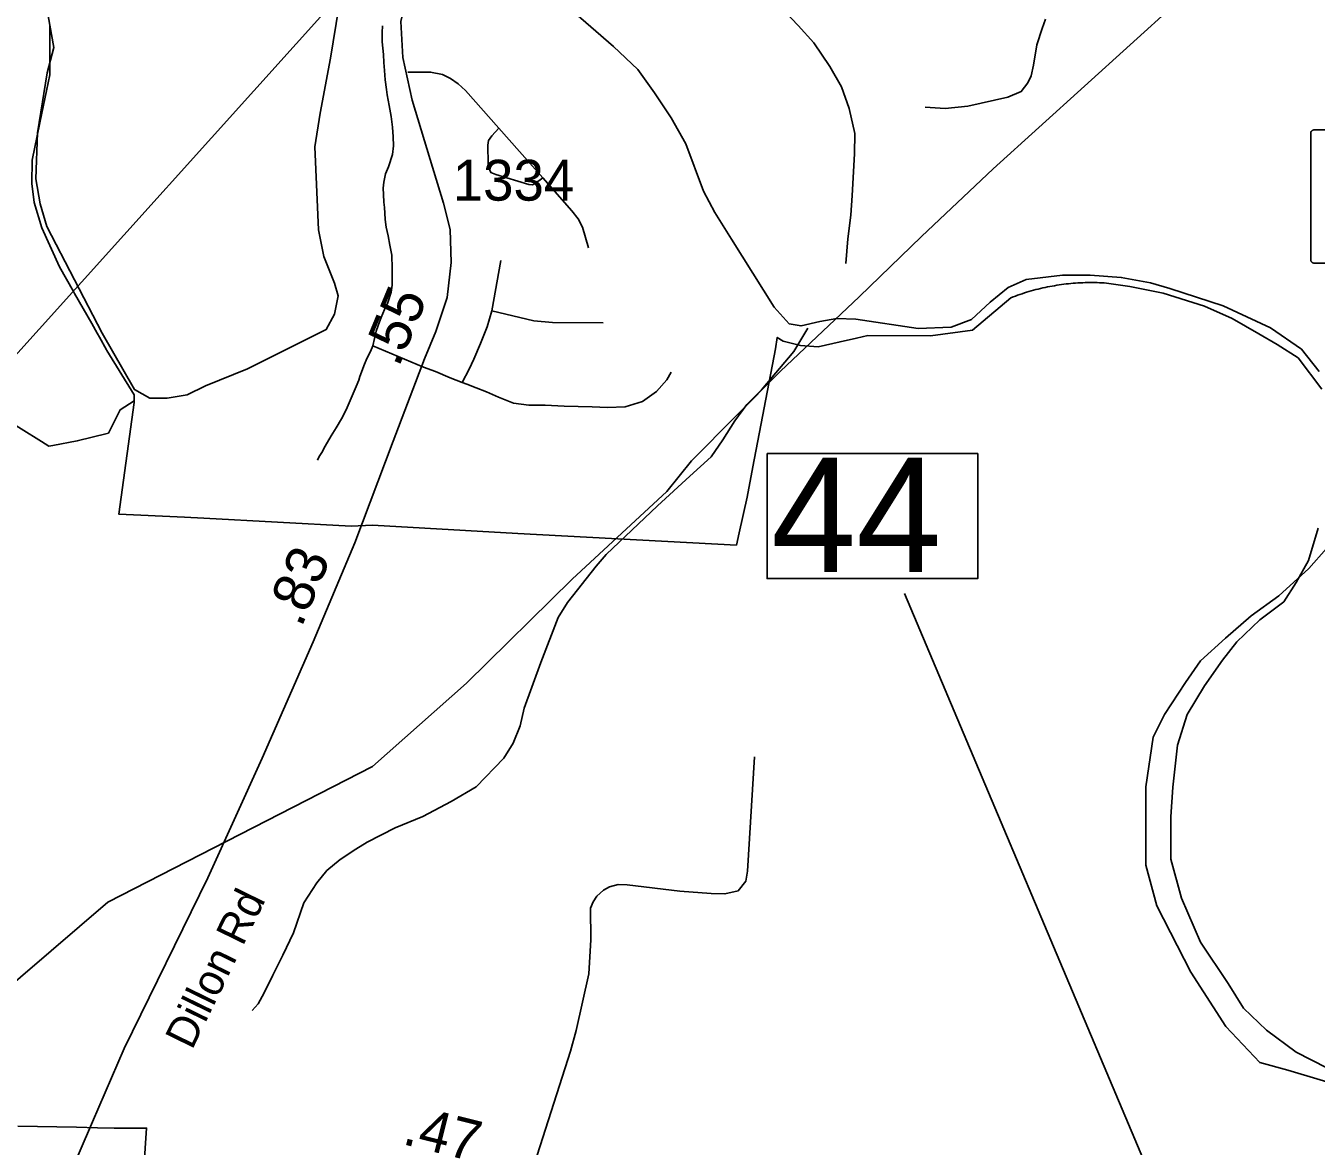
# Model space of a CAD drawing. Extents: x 1662474 to 1856135, y 779280 to 917889.
# Drawn here: x 1720709 to 1724654, y 812795 to 816221 of the extents above; entities that cross this region are included whole.
import ezdxf

# ---------------------------------------------------------------- set-up
doc = ezdxf.new("R2010")
doc.units = 0
for name, color, linetype in [('Exist Boundary Political City Limit New', 7, 'Continuous'), ('Exist Hydrographic Creek Single Shore', 7, 'Continuous'), ('Exist Hydrographic Misc Water Feature', 7, 'Continuous'), ('Exist Road Non-System Type 51', 7, 'Continuous'), ('Exist Road Primary NC Shield Bike CELL', 7, 'Continuous'), ('Exist Road Secondary Mileage Hundredths English Label', 7, 'Continuous'), ('Exist Road Secondary Mileage Tenths English Label', 7, 'Continuous'), ('Exist Road Secondary Structure Standard Bridge Number Label', 7, 'Continuous'), ('Exist Road Secondary Type 51 Attributed', 7, 'Continuous'), ('Exist Road Secondary Type 51 Label', 7, 'Continuous'), ('Exist Road Secondary Type 51 Number Label', 7, 'Continuous'), ('Exist Utilities Electrical Transmission Line', 7, 'Continuous'), ('Map Preparation Boundary City Limit Buffer Line', 7, 'Continuous')]:
    doc.layers.add(name, color=color, linetype=linetype)

msp = doc.modelspace()

# ---------------------------------------------------------------- linework, layer by layer
at = {"layer": 'Exist Boundary Political City Limit New'}
for points in [[(1720782.5, 816222.6), (1720782.4, 816071.8)], [(1720782.4, 816071.8), (1720782.5, 816222.6)], [(1720782.4, 816071.8), (1720782.4, 816071.2), (1720751.6, 815924.1), (1720728.6, 815810.6), (1720728.6, 815810), (1720727.2, 815739.2), (1720727.2, 815738.6), (1720734.4, 815681.2), (1720757.6, 815603.7), (1720811.9, 815484), (1720854.9, 815408.6), (1720858.2, 815402.8), (1720910.4, 815310.6), (1720927.1, 815281.2), (1720934, 815269.1), (1720955.6, 815230.8), (1720957, 815228.3), (1721040.6, 815093.2), (1721040.6, 815092.6), (1721040, 815074.6)], [(1721040, 815074.6), (1721040.6, 815092.6), (1721040.6, 815093.2), (1720957, 815228.3), (1720955.6, 815230.8), (1720934, 815269.1), (1720927.1, 815281.2), (1720910.4, 815310.6), (1720858.2, 815402.8), (1720854.9, 815408.6), (1720811.9, 815484), (1720757.6, 815603.7), (1720734.4, 815681.2), (1720727.2, 815738.6), (1720727.2, 815739.2), (1720728.6, 815810), (1720728.6, 815810.6), (1720751.6, 815924.1), (1720782.4, 816071.2), (1720782.4, 816071.8)], [(1721040, 815074.6), (1721039.9, 815069), (1720993.4, 814727.8), (1721194, 814718.7), (1721252.8, 814716), (1721704, 814691.2), (1721768.5, 814694.5), (1722213.2, 814668.4), (1722881.1, 814633.2), (1722889.4, 814670.6), (1722914.1, 814779.9), (1722931.9, 814872.4), (1723001.2, 815233.5), (1723006.1, 815268.5), (1723023.8, 815256.4), (1723077, 815243.7), (1723131.5, 815239.9), (1723198.4, 815254.9), (1723248.1, 815265.7), (1723282.9, 815273.9), (1723474.1, 815272.7), (1723602.9, 815290.6), (1723720.4, 815389.7), (1723727.1, 815392.2), (1723734, 815394.8), (1723740.8, 815397.2), (1723747.6, 815399.7), (1723754.6, 815402), (1723761.5, 815404.2), (1723768.4, 815406.4), (1723775.4, 815408.5), (1723782.4, 815410.5), (1723789.4, 815412.5), (1723796.4, 815414.4), (1723803.5, 815416.1), (1723810.5, 815417.9), (1723817.6, 815419.5), (1723824.8, 815421), (1723831.9, 815422.5), (1723839, 815423.9), (1723846.1, 815425.2), (1723853.2, 815426.5), (1723860.5, 815427.8), (1723867.6, 815428.8), (1723874.9, 815429.9), (1723882, 815430.8), (1723889.2, 815431.7), (1723896.5, 815432.5), (1723903.8, 815433.2), (1723911, 815433.8), (1723918.2, 815434.4), (1723925.5, 815434.9), (1723932.8, 815435.2), (1723940, 815435.6), (1723947.2, 815435.9), (1723954.5, 815436), (1723961.9, 815436.1), (1723969.1, 815436.1), (1723976.4, 815436), (1723983.6, 815435.9), (1723990.9, 815435.7), (1723998.1, 815435.4), (1724005.4, 815435), (1724012.8, 815434.5), (1724084.2, 815423.5)], [(1724084.2, 815423.5), (1724185.9, 815403.9), (1724311.9, 815363.9), (1724396.6, 815325.9), (1724478.6, 815279.1), (1724534.1, 815246.9), (1724598.5, 815205.9), (1724671.1, 815110.1)], [(1720632.2, 815027.1), (1720756.9, 814949.6), (1720779, 814935.9), (1720791.8, 814938.2), (1720866.2, 814951.8), (1720957.5, 814974.6), (1720961.5, 814975.6), (1720997.2, 815046.9), (1721040, 815074.6)], [(1724659.9, 814685.2), (1724630.6, 814585.8), (1724592.6, 814518.5), (1724554.6, 814460), (1724481.5, 814404.4), (1724411.2, 814337.2), (1724367.4, 814281.6), (1724311.9, 814202.6), (1724259.1, 814114.8), (1724229.9, 814021.2), (1724215.2, 813892.5), (1724209.5, 813801.8), (1724209.5, 813673.1), (1724241.6, 813553.2), (1724300.1, 813418.6), (1724385, 813292.9), (1724431.8, 813216.8), (1724502, 813149.5), (1724592.6, 813082.2), (1724873.5, 812938.9)], [(1721062.6, 812618.5), (1721078, 812850.4), (1721066.4, 812850.5), (1720978.6, 812850.6), (1720927.8, 812850.8), (1720864.2, 812853.4), (1720684.1, 812856.3)]]:
    msp.add_lwpolyline(points, dxfattribs=at)
at = {"layer": 'Exist Hydrographic Creek Single Shore'}
for points in [[(1720766.8, 816309.4), (1720794.4, 816154.8), (1720774.6, 816077.1), (1720744.8, 815893.9), (1720739.8, 815753.5), (1720752.9, 815676.8), (1720773.4, 815607.8), (1720942.6, 815281.6), (1721041.4, 815108.6), (1721088, 815082.9), (1721141.2, 815082.6), (1721202.2, 815092.9), (1721258.1, 815120.1), (1721386.8, 815172.4), (1721627.4, 815292.1), (1721653.1, 815339.8), (1721663.9, 815395.8), (1721653.1, 815433.8), (1721619.5, 815515.7), (1721603.8, 815597.3), (1721592.2, 815850.9), (1721609, 815954.5), (1721640.2, 816122.2), (1721683.2, 816384.7)], [(1722351.2, 816291.5), (1722505.9, 816157.4), (1722579.9, 816087.3), (1722630.5, 816015.7), (1722681.5, 815939.3), (1722726.9, 815859.8), (1722781.1, 815715.4), (1722815.2, 815650.6), (1722866, 815568.7), (1722997.1, 815360.6), (1723042.6, 815309.9), (1723079.1, 815303.4), (1723136, 815316.5), (1723188.2, 815325.7), (1723246.8, 815324.4), (1723436.5, 815295.8), (1723537.9, 815299.9), (1723600.4, 815323.3), (1723657.2, 815376.3), (1723711.9, 815420.7), (1723766.8, 815445.1), (1723878.5, 815458.2), (1723962.5, 815458.2), (1724057.8, 815451.9), (1724147.5, 815435.1), (1724205.9, 815417.8), (1724369.4, 815364.5), (1724513.6, 815297.3), (1724608.8, 815231.9), (1724663.2, 815164.5)], [(1724685.6, 814622.5), (1724630.8, 814561.6), (1724539.9, 814478.2), (1724455.1, 814417.2), (1724376.1, 814348.5), (1724299.5, 814279.2), (1724253.9, 814213.1), (1724190.4, 814115.7), (1724154.9, 814045.4), (1724133.1, 813893.9), (1724132.9, 813654.6)], [(1724132.9, 813654.6), (1724167, 813529.9), (1724270.6, 813327.2), (1724377.8, 813160.9), (1724481.4, 813051.4), (1724567.2, 813028.1), (1724764.6, 812968.2), (1725347.2, 812765.6), (1725471.9, 812747.2), (1725734.4, 812695.2)]]:
    msp.add_lwpolyline(points, dxfattribs=at)
at = {"layer": 'Exist Hydrographic Misc Water Feature'}
for points in [[(1723215.5, 815493.9), (1723222.2, 815569.9), (1723230.8, 815641.8), (1723235.4, 815701.8), (1723242.5, 815829.8), (1723243.1, 815891.8), (1723225.9, 815968), (1723202.5, 816034.2), (1723167.1, 816096.6), (1723117.9, 816169.1), (1723070.3, 816221.6), (1723028.7, 816266), (1722997.1, 816302.2), (1722971.5, 816350.5), (1722947.9, 816400.8), (1722902.4, 816455.2), (1722833, 816521.9), (1722785.5, 816566.3), (1722753.7, 816596.6), (1722741.8, 816610.7)], [(1723099.6, 815297), (1723056.8, 815225.4), (1722957.7, 815108.2), (1722913.2, 815062.7), (1722876.7, 815013), (1722840.2, 814955.3), (1722803.7, 814903.6), (1722739.1, 814844.2), (1722640.1, 814753.1), (1722482.8, 814604.6), (1722452.5, 814568.8), (1722365.3, 814457.6), (1722336.8, 814411.9), (1722283.5, 814274.4), (1722232.2, 814134.8), (1722219.7, 814081), (1722199.2, 814027.1), (1722170.7, 813981.4), (1722085.8, 813894.1), (1722009.4, 813848.9), (1721923, 813803.6), (1721838.5, 813768.4), (1721752.2, 813725.3), (1721718, 813703.6), (1721669.6, 813672), (1721629.4, 813638.4), (1721599, 813600.6), (1721558.4, 813539), (1721527.5, 813447.3), (1721494.9, 813379.5), (1721464.3, 813317.8), (1721437.7, 813264), (1721419.4, 813230.3), (1721401.2, 813210.4)]]:
    msp.add_lwpolyline(points, dxfattribs=at)
at = {"layer": 'Exist Road Non-System Type 51'}
for p, q in [((1722155.4, 815907.8), (1722289.9, 815756.1)), ((1722133.1, 815349.2), (1722161, 815503.6)), ((1721769.9, 815242.7), (1721925, 815177.4))]:
    msp.add_line(p, q, dxfattribs=at)
for points in [[(1721799.6, 816220.9), (1721798.5, 816200.2), (1721798.5, 816172.6), (1721801.9, 816133.5), (1721803.8, 816109.4), (1721805.1, 816084.4), (1721807.6, 816055.9), (1721811.6, 816025.9), (1721813.8, 816009.9), (1721819.8, 815977.6), (1721825.9, 815943.8), (1721830, 815911.2), (1721832.1, 815882.1), (1721833.4, 815854), (1721829.8, 815827.2), (1721817.6, 815790.4), (1721808.5, 815768.4), (1721803.5, 815742.9), (1721801.6, 815724.6), (1721802.1, 815704.9), (1721803.8, 815681.9), (1721805.6, 815665.8), (1721806.1, 815648.5), (1721807.4, 815628.5), (1721810.9, 815605.7), (1721816.9, 815578.9), (1721822.1, 815550.6), (1721827.4, 815520.1), (1721829.1, 815479.2), (1721829.1, 815453.4), (1721828.6, 815428.5), (1721825.9, 815406.8), (1721815.9, 815374.8), (1721805.1, 815353.4), (1721794.9, 815328.8), (1721786.1, 815305.2), (1721780.4, 815287.1), (1721769.9, 815242.7)], [(1723826.6, 816241.9), (1723815.8, 816212.8), (1723800, 816163.4), (1723789.2, 816100.4), (1723782.1, 816068.2), (1723772.5, 816046.4), (1723752, 816020.1), (1723711.4, 816003.4), (1723589.2, 815975.5), (1723519.5, 815968.4), (1723458.4, 815972.4)], [(1721876.8, 816079.2), (1721946.2, 816079.4), (1721982.8, 816071.9), (1722006.9, 816060.2), (1722030.8, 816044), (1722053.4, 816023), (1722155.4, 815907.8)], [(1722155.4, 815907.8), (1722133.4, 815884.7), (1722123.6, 815870.5), (1722120.9, 815856.6), (1722122.1, 815798.6), (1722122.9, 815789.4), (1722131, 815772.1), (1722145.8, 815766.9), (1722246.2, 815735.9), (1722257.6, 815734.6), (1722265.9, 815738.8), (1722289.9, 815756.1)], [(1722289.9, 815756.1), (1722378.5, 815655.6), (1722397.4, 815630.6), (1722411.1, 815605.4), (1722428.6, 815542.4)], [(1722043.1, 815130.4), (1722064.4, 815170.8), (1722078.6, 815201.8), (1722099, 815249.8), (1722119, 815301), (1722133.1, 815349.2)], [(1722133.1, 815349.2), (1722261.5, 815319.1), (1722319.2, 815313.6), (1722474.4, 815312.5)], [(1721769.9, 815242.7), (1721763.1, 815224.9), (1721751.8, 815203.9), (1721742.1, 815181.9), (1721734.8, 815161.9), (1721730.2, 815148.8), (1721726.6, 815137.4), (1721719, 815117.8), (1721700.1, 815075), (1721688, 815047.2), (1721674.1, 815019.6), (1721657.6, 814992.1), (1721642.9, 814966.9), (1721623.6, 814935.4), (1721613.5, 814916.4), (1721605.9, 814903.9), (1721600.6, 814892.6)], [(1721925, 815177.4), (1721961, 815163.7), (1722006.4, 815144.5), (1722043.1, 815130.4)], [(1722043.1, 815130.4), (1722057.2, 815125.7), (1722086.1, 815114.4), (1722117.6, 815101.5), (1722154.1, 815085.5), (1722200.1, 815066.9), (1722246.8, 815060.9), (1722296.6, 815060.9), (1722355.1, 815057.9), (1722398, 815057.2), (1722440.2, 815055.9), (1722487.5, 815053.8), (1722540.8, 815056.4), (1722593.8, 815072.4), (1722637.4, 815103.1), (1722668.6, 815139), (1722681.4, 815161.9)], [(1722226.4, 812631.2), (1722238.9, 812662.9), (1722373.9, 813085.5), (1722391.6, 813148.5), (1722430.5, 813322), (1722436, 813426.5), (1722435.5, 813522.5), (1722443.1, 813541.9), (1722454.4, 813559.5), (1722474.6, 813577.9), (1722492.8, 813587.9), (1722519.5, 813595), (1722547.4, 813593.9), (1722708.4, 813574.8), (1722804, 813567.4), (1722846.2, 813566.4), (1722887.1, 813576.4), (1722910.2, 813605.8), (1722915.2, 813635.9), (1722936.2, 813985.8)]]:
    msp.add_lwpolyline(points, dxfattribs=at)
at = {"layer": 'Exist Road Primary NC Shield Bike CELL'}
msp.add_lwpolyline([(1724680.5, 815495.4), (1724647.6, 815495.4), (1724646.9, 815495.5), (1724646.4, 815495.5), (1724645.7, 815495.6), (1724645, 815495.8), (1724644.3, 815496), (1724643.5, 815496.2), (1724642.8, 815496.6), (1724642.2, 815496.9), (1724641.6, 815497.3), (1724641, 815497.7), (1724640.7, 815498), (1724640.3, 815498.3), (1724640, 815498.6), (1724639.6, 815499.1), (1724639.2, 815499.5), (1724638.9, 815499.9), (1724638.6, 815500.4), (1724638.3, 815500.8), (1724638, 815501.3), (1724637.8, 815501.9), (1724637.6, 815502.4), (1724637.4, 815502.7), (1724637.3, 815503), (1724637.3, 815503.2), (1724637.2, 815503.4), (1724637.1, 815503.7), (1724637.1, 815503.9), (1724637, 815504.2), (1724637, 815504.4), (1724637, 815504.7), (1724636.9, 815504.9), (1724636.9, 815505.1), (1724636.9, 815505.4), (1724636.8, 815506), (1724636.8, 815539.2), (1724636.8, 815859.1), (1724636.8, 815892.1), (1724636.9, 815893.3), (1724637, 815893.9), (1724637.2, 815894.7), (1724637.4, 815895.4), (1724637.6, 815896.1), (1724638.3, 815897.5), (1724638.7, 815898.1), (1724639.1, 815898.7), (1724639.8, 815899.4), (1724640.8, 815900.4), (1724641.6, 815901), (1724642, 815901.2), (1724642.4, 815901.5), (1724642.9, 815901.7), (1724643.3, 815901.9), (1724643.8, 815902.1), (1724644.5, 815902.4), (1724645.4, 815902.6), (1724646.3, 815902.8), (1724646.7, 815902.8), (1724647.5, 815902.9), (1724680.5, 815902.9)], dxfattribs=at)
at = {"layer": 'Exist Road Secondary Structure Standard Bridge Number Label'}
for p, q in [((1721764.9, 816421.7), (1720248.9, 814737.3)), ((1724396.9, 812110.6), (1723395.2, 814484.8))]:
    msp.add_line(p, q, dxfattribs=at)
msp.add_lwpolyline([(1722974.9, 814913.3), (1723619, 814913.3), (1723619, 814531), (1722974.9, 814531)], close=True, dxfattribs=at)
at = {"layer": 'Exist Road Secondary Type 51 Attributed'}
msp.add_lwpolyline([(1720784, 812571.2), (1720912.6, 812869.4), (1721009.3, 813093.4), (1721265, 813615.5), (1721431.7, 813982.1), (1721587.4, 814337.6), (1721715.2, 814639.7), (1721831.9, 814950.7), (1721928, 815202.4), (1721962.7, 815286.2), (1721997.4, 815390.2), (1722009, 815497.2), (1722006.1, 815598.3), (1721985.8, 815679.2), (1721945.3, 815812.1), (1721890.4, 815994.1), (1721861.5, 816124.1), (1721855.7, 816233.9), (1721881.7, 816347.2), (1721913.5, 816445.4), (1721949.3, 816526.9), (1721979.6, 816588.7)], dxfattribs=at)
at = {"layer": 'Exist Utilities Electrical Transmission Line'}
msp.add_lwpolyline([(1716438.8, 809461.3), (1716787.4, 809798.2), (1717249.4, 810227.3), (1717691.2, 810629), (1718049.5, 810965.7), (1718432.3, 811308.1), (1718833.1, 811664), (1719416.5, 812185.8), (1719829.3, 812547.7), (1720090.8, 812785.9), (1720518, 813163.6), (1720959.3, 813541.3), (1721768.9, 813955.8), (1722056.4, 814211.5), (1722378.9, 814528.9), (1722668.3, 814796.8), (1722743.8, 814891.4), (1723015.9, 815165.2), (1723256.8, 815392.1), (1723447.4, 815577.2), (1723666.2, 815783.8), (1724225, 816289.8)], dxfattribs=at)
at = {"layer": 'Map Preparation Boundary City Limit Buffer Line'}
for points in [[(1720782.5, 816222.6), (1720782.4, 816071.8)], [(1720782.4, 816071.8), (1720782.5, 816222.6)], [(1720782.4, 816071.8), (1720782.4, 816071.2), (1720751.6, 815924.1), (1720728.6, 815810.6), (1720728.6, 815810), (1720727.2, 815739.2), (1720727.2, 815738.6), (1720734.4, 815681.2), (1720757.6, 815603.7), (1720811.9, 815484), (1720854.9, 815408.6), (1720858.2, 815402.8), (1720910.4, 815310.6), (1720927.1, 815281.2), (1720934, 815269.1), (1720955.6, 815230.8), (1720957, 815228.3), (1721040.6, 815093.2), (1721040.6, 815092.6), (1721040, 815074.6)], [(1721040, 815074.6), (1721040.6, 815092.6), (1721040.6, 815093.2), (1720957, 815228.3), (1720955.6, 815230.8), (1720934, 815269.1), (1720927.1, 815281.2), (1720910.4, 815310.6), (1720858.2, 815402.8), (1720854.9, 815408.6), (1720811.9, 815484), (1720757.6, 815603.7), (1720734.4, 815681.2), (1720727.2, 815738.6), (1720727.2, 815739.2), (1720728.6, 815810), (1720728.6, 815810.6), (1720751.6, 815924.1), (1720782.4, 816071.2), (1720782.4, 816071.8)], [(1721040, 815074.6), (1721039.9, 815069), (1720993.4, 814727.8), (1721194, 814718.7), (1721252.8, 814716), (1721704, 814691.2), (1721768.5, 814694.5), (1722213.2, 814668.4), (1722881.1, 814633.2), (1722889.4, 814670.6), (1722914.1, 814779.9), (1722931.9, 814872.4), (1723001.2, 815233.5), (1723006.1, 815268.5), (1723023.8, 815256.4), (1723077, 815243.7), (1723131.5, 815239.9), (1723198.4, 815254.9), (1723248.1, 815265.7), (1723282.9, 815273.9), (1723474.1, 815272.7), (1723602.9, 815290.6), (1723720.4, 815389.7), (1723727.1, 815392.2), (1723734, 815394.8), (1723740.8, 815397.2), (1723747.6, 815399.7), (1723754.6, 815402), (1723761.5, 815404.2), (1723768.4, 815406.4), (1723775.4, 815408.5), (1723782.4, 815410.5), (1723789.4, 815412.5), (1723796.4, 815414.4), (1723803.5, 815416.1), (1723810.5, 815417.9), (1723817.6, 815419.5), (1723824.8, 815421), (1723831.9, 815422.5), (1723839, 815423.9), (1723846.1, 815425.2), (1723853.2, 815426.5), (1723860.5, 815427.8), (1723867.6, 815428.8), (1723874.9, 815429.9), (1723882, 815430.8), (1723889.2, 815431.7), (1723896.5, 815432.5), (1723903.8, 815433.2), (1723911, 815433.8), (1723918.2, 815434.4), (1723925.5, 815434.9), (1723932.8, 815435.2), (1723940, 815435.6), (1723947.2, 815435.9), (1723954.5, 815436), (1723961.9, 815436.1), (1723969.1, 815436.1), (1723976.4, 815436), (1723983.6, 815435.9), (1723990.9, 815435.7), (1723998.1, 815435.4), (1724005.4, 815435), (1724012.8, 815434.5), (1724084.2, 815423.5)], [(1724084.2, 815423.5), (1724185.9, 815403.9), (1724311.9, 815363.9), (1724396.6, 815325.9), (1724478.6, 815279.1), (1724534.1, 815246.9), (1724598.5, 815205.9), (1724671.1, 815110.1)], [(1720632.2, 815027.1), (1720756.9, 814949.6), (1720779, 814935.9), (1720791.8, 814938.2), (1720866.2, 814951.8), (1720957.5, 814974.6), (1720961.5, 814975.6), (1720997.2, 815046.9), (1721040, 815074.6)], [(1724659.9, 814685.2), (1724630.6, 814585.8), (1724592.6, 814518.5), (1724554.6, 814460), (1724481.5, 814404.4), (1724411.2, 814337.2), (1724367.4, 814281.6), (1724311.9, 814202.6), (1724259.1, 814114.8), (1724229.9, 814021.2), (1724215.2, 813892.5), (1724209.5, 813801.8), (1724209.5, 813673.1), (1724241.6, 813553.2), (1724300.1, 813418.6), (1724385, 813292.9), (1724431.8, 813216.8), (1724502, 813149.5), (1724592.6, 813082.2), (1724873.5, 812938.9)], [(1721062.6, 812618.5), (1721078, 812850.4), (1721066.4, 812850.5), (1720978.6, 812850.6), (1720927.8, 812850.8), (1720864.2, 812853.4), (1720684.1, 812856.3)]]:
    msp.add_lwpolyline(points, dxfattribs=at)

# ---------------------------------------------------------------- texts
at = {"layer": 'Exist Road Secondary Mileage Hundredths English Label'}
msp.add_text('.55', height=125, rotation=67.5052, dxfattribs=at).set_placement((1721848.6, 815174.1))
at = {"layer": 'Exist Road Secondary Mileage Tenths English Label'}
for s, rotation, p in [('.83', 67.0657, (1721551.2, 814378.4)), ('.47', 345.9739, (1721856.7, 812802.4))]:
    msp.add_text(s, height=125, rotation=rotation, dxfattribs=at).set_placement(p)
at = {"layer": 'Exist Road Secondary Structure Standard Bridge Number Label'}
msp.add_text('44', height=350, dxfattribs=at).set_placement((1722987.4, 814550.8))
at = {"layer": 'Exist Road Secondary Type 51 Label'}
msp.add_text('Dillon Rd', height=95, rotation=63.9137, dxfattribs=at).set_placement((1721216.8, 813087))
at = {"layer": 'Exist Road Secondary Type 51 Number Label'}
msp.add_text('1334', height=125, dxfattribs=at).set_placement((1722013.9, 815686.5))

doc.saveas('drawing.dxf')
